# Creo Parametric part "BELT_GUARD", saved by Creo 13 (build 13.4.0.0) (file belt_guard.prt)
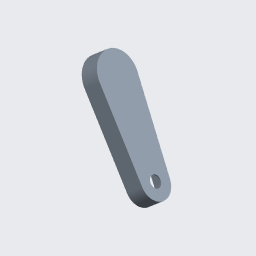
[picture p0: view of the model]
Units: millimeter Newton Second (mmNs); MM, TONNE, SECS

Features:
  1. datum plane "RIGHT"
  2. datum plane "TOP"
  3. datum plane "FRONT"
  4. coordinate system
  5. protrusion
  6. cut
  7. datum axis
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
Other named items: PRT_CSYS_DEF_1, PRT_CSYS_DEF_2, PRT_CSYS_DEF_3, PRT_CSYS_DEF_4

Surfaces: 11 plane, 8 cylinder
